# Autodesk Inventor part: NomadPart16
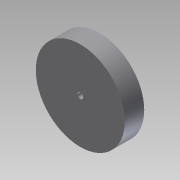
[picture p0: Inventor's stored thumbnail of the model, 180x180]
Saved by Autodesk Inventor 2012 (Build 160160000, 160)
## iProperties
Created: 2012-10
Part Number: NomadPart16
Material: Default
Document SubType Name: Modeling
Designer: TechShop Member
Density: 1 g/cm^3
Author: TechShop Member
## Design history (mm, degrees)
sketch "Sketch1"
  geometry: C1 r 39.497 at (0, 0); 1 further point
  constraints: 1 centre point, 1 coincident
  dimensions: "d0" = 78.994 diameter of C1
extrude "Extrusion1" new body sketch "Sketch1" distance "d1" = 17.272; taper "d2" = 0 deg
sketch "Sketch2"
  geometry: C1 r 39.497 at (0, 0) reference; 1 further point
  constraints: 1 coincident
hole "Hole1" sketch "Sketch2" at (0, 0) diameter "d3" = 5.207; stored, may be unused: countersink angle "d7" = 82 deg, drill point angle "d9" = 118 deg; dims "d4" = 19.05, "d5" = 9.525, "d6" = 6.35, "d8" = 25.4
body "Solid1"
